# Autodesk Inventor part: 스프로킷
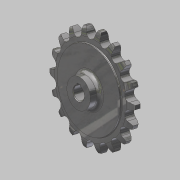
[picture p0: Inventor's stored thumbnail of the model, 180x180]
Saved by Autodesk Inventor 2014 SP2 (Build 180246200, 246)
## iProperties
Created: 2016-03
Part Number: 스프로킷
Material: 강철, 탄소
Document SubType Name: Modeling
Designer: mduedu
Density: 7.87 g/cm^3
Appearance: 반광택
Author: mduedu
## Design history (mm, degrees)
sketch "스케치1"
  geometry: L1 (0, 5)-(29.5, 5); L2 (29.5, 5)-(29.5, 4.1); L3 (30, 3.6)-(33.625, 3.6); L4 (40, 2)-(40, 0); L5 (40, 0)-(0, 0); L6 (0, 0)-(0, 5); L7 (0, -5)-(29.5, -5); L8 (29.5, -5)-(29.5, -4.1); L9 (30, -3.6)-(33.625, -3.6); L10 (40, -2)-(40, 0); L11 (0, 0)-(0, -5); A1 r 13.5 centre (33.625, -9.9) between (40, 2) and (33.625, 3.6); A2 r 13.5 centre (33.625, 9.9) between (33.625, -3.6) and (40, -2); A3 r 0.5 centre (30, 4.1) between (29.5, 4.1) and (30, 3.6); A4 r 0.5 centre (30, -4.1) between (30, -3.6) and (29.5, -4.1); 2 further points
  constraints: 22 end point, 8 point on circle, 6 symmetric about line, 5 tangent, 4 centre point, 4 parallel, 4 point on line, 1 equal radius, 1 horizontal, 1 perpendicular, 1 other
  dimensions: "d0" = 80 diameter of L4 L6; "d2" = 59 diameter of L2 L6; "d3" = 1.6 vertical distance of L4.start L3.end; "d4" = 3.6 distance from line of L4.end L3; "d5" = 5 distance between parallel lines of L5 L1; "d6" = 13.5 radius of A1; "d15" = 0.5 radius of A3
revolve "회전1" sketch "스케치1" stored, may be unused: angle "d7" = 90 deg
sketch "스케치2" dims "d8" = 65.2, "d11" = 80
  geometry: L1 (0, 0)-(0, 32.6); A1 r 36.57 centre (0, 0) between (-16.231, 32.771) and (0, 36.57); A2 r 3.97 centre (0, 36.57) between (-3.866, 35.665) and (0, 32.6); A3 r 12.7 centre (-16.231, 32.771) between (-3.866, 35.665) and (-5.534, 39.615); A4 r 12.7 centre (16.231, 32.771) between (5.534, 39.615) and (3.866, 35.665); A5 r 3.97 centre (0, 36.57) between (0, 32.6) and (3.866, 35.665); A6 r 40 centre (0, 0) between (5.534, 39.615) and (-5.534, 39.615); 2 further points
  constraints: 12 point on circle, 6 centre point, 4 coincident, 3 symmetric about line, 2 end point, 1 point on line, 1 tangent, 1 vertical, 1 vertical alignment, 7 other
  dimensions: "d10" = 73.14 diameter of A1; "d12" = 12.7 radius of A3
extrude "돌출1" cut sketch "스케치2" stored distance "d13" = 10; taper "d14" = 0 deg
sketch "스케치3"
  geometry: C1 r 11 at (0, 0); 1 further point
  constraints: 1 centre point, 1 coincident
  dimensions: "d19" = 22 diameter of C1
extrude "돌출2" join sketch "스케치3" distance "d20" = 8; taper "d21" = 0 deg
fillet "모깎기1" dims "d22" = 3
sketch "스케치4"
  geometry: L1 (-1.5, 0)-(1.5, 0); L2 (1.5, 0)-(1.5, 6.4); L3 (1.5, 6.4)-(-1.5, 6.4); L4 (-1.5, 6.4)-(-1.5, 0); C1 r 5 at (0, 0); 2 further points
  constraints: 8 end point, 2 coincident, 2 parallel, 1 centre point, 1 horizontal, 1 midpoint, 1 perpendicular
  dimensions: "d23" = 10 diameter of C1; "d25" = 3 distance of L2.end L3.end; "d26" = 6.4 distance of L1.end L2.end
extrude "돌출3" cut sketch "스케치4" stored distance "d27" = 8; taper "d28" = 0 deg
chamfer "모따기1" distance "d29" = 0.5; stored, may be unused: second distance "d30" = 2, angle "d31" = 45 deg
node "솔리드1"
pattern_circular "원형 패턴1" dims angle "d17" = 360 deg
